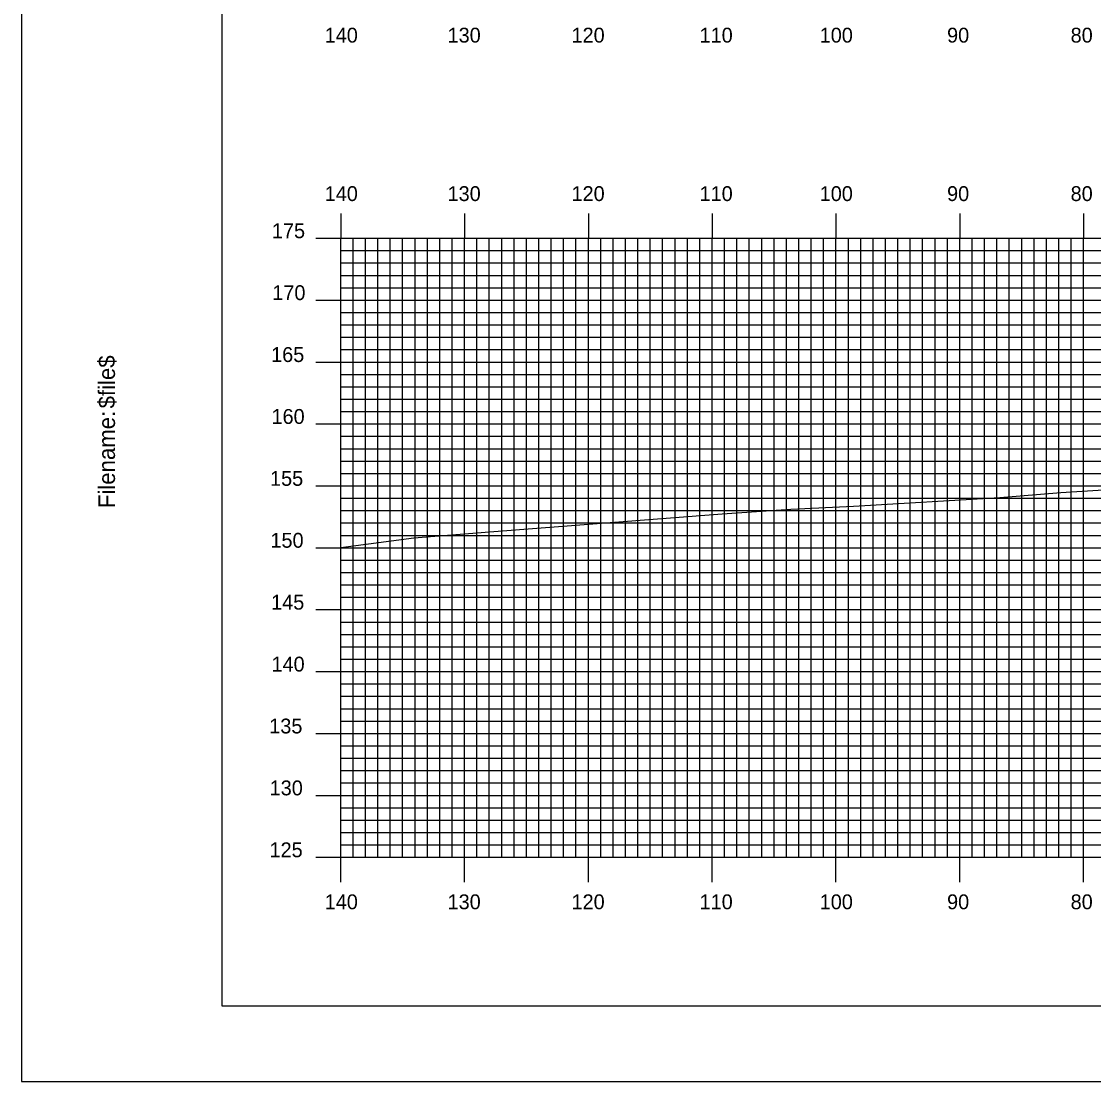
# Model space of a CAD drawing. Extents: x 1783434 to 1783777, y 442591 to 442811.
# Drawn here: x 1783434.2 to 1783520.8, y 442590.5 to 442676.2 of the extents above; entities that cross this region are included whole.
import ezdxf

# ---------------------------------------------------------------- set-up
doc = ezdxf.new("R2010")
doc.units = 0
for name, color, linetype in [('BORDER', 7, 'Continuous'), ('H_V ANNOTATION', 7, 'Continuous'), ('MAJOR', 7, 'Continuous'), ('MINOR', 7, 'Continuous'), ('PLOT BOUNDARY', 7, 'Continuous'), ('S_Roadway_Centerline', 7, 'Continuous')]:
    doc.layers.add(name, color=color, linetype=linetype)

msp = doc.modelspace()

# ---------------------------------------------------------------- linework, layer by layer
at = {"layer": 'BORDER'}
msp.add_lwpolyline([(1783450.373, 442596.665), (1783770.373, 442596.665), (1783770.373, 442806.665), (1783450.373, 442806.665)], close=True, dxfattribs=at)
at = {"layer": 'MAJOR'}
for p, q in [((1783459.973, 442660.669), (1783459.973, 442658.665)), ((1783469.973, 442660.669), (1783469.973, 442658.665)), ((1783479.973, 442660.669), (1783479.973, 442658.665)), ((1783489.973, 442660.669), (1783489.973, 442658.665)), ((1783499.973, 442660.669), (1783499.973, 442658.665)), ((1783509.973, 442660.669), (1783509.973, 442658.665)), ((1783519.973, 442660.669), (1783519.973, 442658.665)), ((1783457.969, 442658.665), (1783459.973, 442658.665)), ((1783459.973, 442658.665), (1783739.973, 442658.665)), ((1783459.973, 442608.665), (1783459.973, 442658.665)), ((1783459.973, 442608.665), (1783459.973, 442658.665)), ((1783459.973, 442658.665), (1783739.973, 442658.665)), ((1783469.973, 442608.665), (1783469.973, 442658.665)), ((1783479.973, 442608.665), (1783479.973, 442658.665)), ((1783489.973, 442608.665), (1783489.973, 442658.665)), ((1783499.973, 442608.665), (1783499.973, 442658.665)), ((1783509.973, 442608.665), (1783509.973, 442658.665)), ((1783519.973, 442608.665), (1783519.973, 442658.665)), ((1783457.969, 442653.665), (1783459.973, 442653.665)), ((1783459.973, 442653.665), (1783739.973, 442653.665)), ((1783457.969, 442648.665), (1783459.973, 442648.665)), ((1783459.973, 442648.665), (1783739.973, 442648.665)), ((1783457.969, 442643.665), (1783459.973, 442643.665)), ((1783459.973, 442643.665), (1783739.973, 442643.665)), ((1783457.969, 442638.665), (1783459.973, 442638.665)), ((1783459.973, 442638.665), (1783739.973, 442638.665)), ((1783457.969, 442633.665), (1783459.973, 442633.665)), ((1783459.973, 442633.665), (1783739.973, 442633.665)), ((1783457.969, 442628.665), (1783459.973, 442628.665)), ((1783459.973, 442628.665), (1783739.973, 442628.665)), ((1783457.969, 442623.665), (1783459.973, 442623.665)), ((1783459.973, 442623.665), (1783739.973, 442623.665)), ((1783457.969, 442618.665), (1783459.973, 442618.665)), ((1783459.973, 442618.665), (1783739.973, 442618.665)), ((1783457.969, 442613.665), (1783459.973, 442613.665)), ((1783459.973, 442613.665), (1783739.973, 442613.665)), ((1783457.969, 442608.665), (1783459.973, 442608.665)), ((1783459.973, 442608.665), (1783739.973, 442608.665)), ((1783459.973, 442608.665), (1783739.973, 442608.665)), ((1783459.973, 442606.661), (1783459.973, 442608.665)), ((1783469.973, 442606.661), (1783469.973, 442608.665)), ((1783479.973, 442606.661), (1783479.973, 442608.665)), ((1783489.973, 442606.661), (1783489.973, 442608.665)), ((1783499.973, 442606.661), (1783499.973, 442608.665)), ((1783509.973, 442606.661), (1783509.973, 442608.665)), ((1783519.973, 442606.661), (1783519.973, 442608.665))]:
    msp.add_line(p, q, dxfattribs=at)
at = {"layer": 'MINOR'}
for p, q in [((1783460.973, 442608.665), (1783460.973, 442658.665)), ((1783461.973, 442608.665), (1783461.973, 442658.665)), ((1783462.973, 442608.665), (1783462.973, 442658.665)), ((1783463.973, 442608.665), (1783463.973, 442658.665)), ((1783464.973, 442608.665), (1783464.973, 442658.665)), ((1783465.973, 442608.665), (1783465.973, 442658.665)), ((1783466.973, 442608.665), (1783466.973, 442658.665)), ((1783467.973, 442608.665), (1783467.973, 442658.665)), ((1783468.973, 442608.665), (1783468.973, 442658.665)), ((1783470.973, 442608.665), (1783470.973, 442658.665)), ((1783471.973, 442608.665), (1783471.973, 442658.665)), ((1783472.973, 442608.665), (1783472.973, 442658.665)), ((1783473.973, 442608.665), (1783473.973, 442658.665)), ((1783474.973, 442608.665), (1783474.973, 442658.665)), ((1783475.973, 442608.665), (1783475.973, 442658.665)), ((1783476.973, 442608.665), (1783476.973, 442658.665)), ((1783477.973, 442608.665), (1783477.973, 442658.665)), ((1783478.973, 442608.665), (1783478.973, 442658.665)), ((1783480.973, 442608.665), (1783480.973, 442658.665)), ((1783481.973, 442608.665), (1783481.973, 442658.665)), ((1783482.973, 442608.665), (1783482.973, 442658.665)), ((1783483.973, 442608.665), (1783483.973, 442658.665)), ((1783484.973, 442608.665), (1783484.973, 442658.665)), ((1783485.973, 442608.665), (1783485.973, 442658.665)), ((1783486.973, 442608.665), (1783486.973, 442658.665)), ((1783487.973, 442608.665), (1783487.973, 442658.665)), ((1783488.973, 442608.665), (1783488.973, 442658.665)), ((1783490.973, 442608.665), (1783490.973, 442658.665)), ((1783491.973, 442608.665), (1783491.973, 442658.665)), ((1783492.973, 442608.665), (1783492.973, 442658.665)), ((1783493.973, 442608.665), (1783493.973, 442658.665)), ((1783494.973, 442608.665), (1783494.973, 442658.665)), ((1783495.973, 442608.665), (1783495.973, 442658.665)), ((1783496.973, 442608.665), (1783496.973, 442658.665)), ((1783497.973, 442608.665), (1783497.973, 442658.665)), ((1783498.973, 442608.665), (1783498.973, 442658.665)), ((1783500.973, 442608.665), (1783500.973, 442658.665)), ((1783501.973, 442608.665), (1783501.973, 442658.665)), ((1783502.973, 442608.665), (1783502.973, 442658.665)), ((1783503.973, 442608.665), (1783503.973, 442658.665)), ((1783504.973, 442608.665), (1783504.973, 442658.665)), ((1783505.973, 442608.665), (1783505.973, 442658.665)), ((1783506.973, 442608.665), (1783506.973, 442658.665)), ((1783507.973, 442608.665), (1783507.973, 442658.665)), ((1783508.973, 442608.665), (1783508.973, 442658.665)), ((1783510.973, 442608.665), (1783510.973, 442658.665)), ((1783511.973, 442608.665), (1783511.973, 442658.665)), ((1783512.973, 442608.665), (1783512.973, 442658.665)), ((1783513.973, 442608.665), (1783513.973, 442658.665)), ((1783514.973, 442608.665), (1783514.973, 442658.665)), ((1783515.973, 442608.665), (1783515.973, 442658.665)), ((1783516.973, 442608.665), (1783516.973, 442658.665)), ((1783517.973, 442608.665), (1783517.973, 442658.665)), ((1783518.973, 442608.665), (1783518.973, 442658.665)), ((1783459.973, 442657.665), (1783739.973, 442657.665)), ((1783459.973, 442657.665), (1783461.977, 442657.665)), ((1783459.973, 442656.665), (1783739.973, 442656.665)), ((1783459.973, 442656.665), (1783461.977, 442656.665)), ((1783459.973, 442655.665), (1783739.973, 442655.665)), ((1783459.973, 442655.665), (1783461.977, 442655.665)), ((1783459.973, 442654.665), (1783739.973, 442654.665)), ((1783459.973, 442654.665), (1783461.977, 442654.665)), ((1783459.973, 442652.665), (1783739.973, 442652.665)), ((1783459.973, 442652.665), (1783461.977, 442652.665)), ((1783459.973, 442651.665), (1783739.973, 442651.665)), ((1783459.973, 442651.665), (1783461.977, 442651.665)), ((1783459.973, 442650.665), (1783739.973, 442650.665)), ((1783459.973, 442650.665), (1783461.977, 442650.665)), ((1783459.973, 442649.665), (1783739.973, 442649.665)), ((1783459.973, 442649.665), (1783461.977, 442649.665)), ((1783459.973, 442647.665), (1783739.973, 442647.665)), ((1783459.973, 442647.665), (1783461.977, 442647.665)), ((1783459.973, 442646.665), (1783739.973, 442646.665)), ((1783459.973, 442646.665), (1783461.977, 442646.665)), ((1783459.973, 442645.665), (1783739.973, 442645.665)), ((1783459.973, 442645.665), (1783461.977, 442645.665)), ((1783459.973, 442644.665), (1783739.973, 442644.665)), ((1783459.973, 442644.665), (1783461.977, 442644.665)), ((1783459.973, 442642.665), (1783739.973, 442642.665)), ((1783459.973, 442642.665), (1783461.977, 442642.665)), ((1783459.973, 442641.665), (1783739.973, 442641.665)), ((1783459.973, 442641.665), (1783461.977, 442641.665)), ((1783459.973, 442640.665), (1783739.973, 442640.665)), ((1783459.973, 442640.665), (1783461.977, 442640.665)), ((1783459.973, 442639.665), (1783739.973, 442639.665)), ((1783459.973, 442639.665), (1783461.977, 442639.665)), ((1783459.973, 442637.665), (1783739.973, 442637.665)), ((1783459.973, 442637.665), (1783461.977, 442637.665)), ((1783459.973, 442636.665), (1783739.973, 442636.665)), ((1783459.973, 442636.665), (1783461.977, 442636.665)), ((1783459.973, 442635.665), (1783739.973, 442635.665)), ((1783459.973, 442635.665), (1783461.977, 442635.665)), ((1783459.973, 442634.665), (1783739.973, 442634.665)), ((1783459.973, 442634.665), (1783461.977, 442634.665)), ((1783459.973, 442632.665), (1783739.973, 442632.665)), ((1783459.973, 442632.665), (1783461.977, 442632.665)), ((1783459.973, 442631.665), (1783739.973, 442631.665)), ((1783459.973, 442631.665), (1783461.977, 442631.665)), ((1783459.973, 442630.665), (1783739.973, 442630.665)), ((1783459.973, 442630.665), (1783461.977, 442630.665)), ((1783459.973, 442629.665), (1783739.973, 442629.665)), ((1783459.973, 442629.665), (1783461.977, 442629.665)), ((1783459.973, 442627.665), (1783739.973, 442627.665)), ((1783459.973, 442627.665), (1783461.977, 442627.665)), ((1783459.973, 442626.665), (1783739.973, 442626.665)), ((1783459.973, 442626.665), (1783461.977, 442626.665)), ((1783459.973, 442625.665), (1783739.973, 442625.665)), ((1783459.973, 442625.665), (1783461.977, 442625.665)), ((1783459.973, 442624.665), (1783739.973, 442624.665)), ((1783459.973, 442624.665), (1783461.977, 442624.665)), ((1783459.973, 442622.665), (1783739.973, 442622.665)), ((1783459.973, 442622.665), (1783461.977, 442622.665)), ((1783459.973, 442621.665), (1783739.973, 442621.665)), ((1783459.973, 442621.665), (1783461.977, 442621.665)), ((1783459.973, 442620.665), (1783739.973, 442620.665)), ((1783459.973, 442620.665), (1783461.977, 442620.665)), ((1783459.973, 442619.665), (1783739.973, 442619.665)), ((1783459.973, 442619.665), (1783461.977, 442619.665)), ((1783459.973, 442617.665), (1783739.973, 442617.665)), ((1783459.973, 442617.665), (1783461.977, 442617.665)), ((1783459.973, 442616.665), (1783739.973, 442616.665)), ((1783459.973, 442616.665), (1783461.977, 442616.665)), ((1783459.973, 442615.665), (1783739.973, 442615.665)), ((1783459.973, 442615.665), (1783461.977, 442615.665)), ((1783459.973, 442614.665), (1783739.973, 442614.665)), ((1783459.973, 442614.665), (1783461.977, 442614.665)), ((1783459.973, 442612.665), (1783739.973, 442612.665)), ((1783459.973, 442612.665), (1783461.977, 442612.665)), ((1783459.973, 442611.665), (1783739.973, 442611.665)), ((1783459.973, 442611.665), (1783461.977, 442611.665)), ((1783459.973, 442610.665), (1783739.973, 442610.665)), ((1783459.973, 442610.665), (1783461.977, 442610.665)), ((1783459.973, 442609.665), (1783739.973, 442609.665)), ((1783459.973, 442609.665), (1783461.977, 442609.665))]:
    msp.add_line(p, q, dxfattribs=at)
at = {"layer": 'PLOT BOUNDARY'}
msp.add_lwpolyline([(1783434.187, 442590.547), (1783774.187, 442590.547), (1783774.187, 442810.547), (1783434.187, 442810.547)], close=True, dxfattribs=at)
at = {"layer": 'S_Roadway_Centerline'}
msp.add_lwpolyline([(1783459.973, 442633.683), (1783465.872, 442634.458), (1783471.993, 442634.957), (1783490.784, 442636.412), (1783496.321, 442636.766), (1783501.377, 442637.028), (1783513.215, 442637.72), (1783518.126, 442638.126), (1783524.591, 442638.528), (1783530.762, 442638.848), (1783537.109, 442639.571), (1783546.695, 442640.563), (1783559.882, 442641.384), (1783568.804, 442641.876), (1783576.309, 442642.557), (1783584.326, 442643.373), (1783588.105, 442643.838), (1783591.766, 442644.058), (1783600.645, 442644.517), (1783608.677, 442644.949), (1783615.822, 442645.3), (1783631.832, 442646.263)], dxfattribs=at)

# ---------------------------------------------------------------- texts
at = {"layer": 'BORDER'}
for s, p in [('$file$', (1783441.743, 442644.916)), ('$file$', (1783441.743, 442644.916)), ('Filename:', (1783441.743, 442636.862)), ('Filename:', (1783441.743, 442636.862))]:
    msp.add_text(s, height=1.3392, rotation=90, dxfattribs=at).set_placement(p)
at = {"layer": 'H_V ANNOTATION'}
for s, p in [('140', (1783458.678, 442674.465)), ('130', (1783468.603, 442674.465)), ('120', (1783478.614, 442674.465)), ('110', (1783488.956, 442674.465)), ('100', (1783498.657, 442674.465)), ('90', (1783508.946, 442674.465)), ('80', (1783518.924, 442674.465)), ('140', (1783458.678, 442661.665)), ('130', (1783468.603, 442661.665)), ('120', (1783478.614, 442661.665)), ('110', (1783488.956, 442661.665)), ('100', (1783498.657, 442661.665)), ('90', (1783508.946, 442661.665)), ('80', (1783518.924, 442661.665)), ('175', (1783454.415, 442658.665)), ('170', (1783454.447, 442653.665)), ('165', (1783454.351, 442648.665)), ('160', (1783454.383, 442643.665)), ('155', (1783454.265, 442638.665)), ('150', (1783454.297, 442633.665)), ('145', (1783454.351, 442628.665)), ('140', (1783454.383, 442623.665)), ('135', (1783454.201, 442618.665)), ('130', (1783454.233, 442613.665)), ('125', (1783454.222, 442608.665)), ('140', (1783458.678, 442604.465)), ('130', (1783468.603, 442604.465)), ('120', (1783478.614, 442604.465)), ('110', (1783488.956, 442604.465)), ('100', (1783498.657, 442604.465)), ('90', (1783508.946, 442604.465)), ('80', (1783518.924, 442604.465))]:
    msp.add_text(s, height=1.2, dxfattribs=at).set_placement(p)
at = {"layer": 'MAJOR'}
msp.add_text('-', height=0.012, dxfattribs=at).set_placement((1783459.964, 442608.665))

doc.saveas('drawing.dxf')
